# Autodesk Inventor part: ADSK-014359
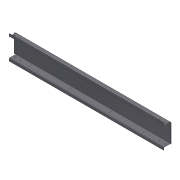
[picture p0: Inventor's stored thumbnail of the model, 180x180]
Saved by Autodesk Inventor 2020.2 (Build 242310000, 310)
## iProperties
Created: 2000-02
Part Number: ADSK-014359
Document SubType Name: Tôlerie
Designer: gpurviance
Material: 1.0312 DC05
Density: 1 g/cm^3
Sheet Metal Rule: Stahlblech 1.0312 - DC05 -   3.0 mm
Appearance: Metal-Steel(Polish)
Mass: 2976.02 g
Surface Area: 20026.5 cm^2
Volume: 2976.02 cm^3
Sheet Metal Width: 483,143 mm
Sheet Metal Length: 2072,093 mm
Sheet Metal Area: 1001118,030 mm^2
Flat Pattern Width: 48.3143 cm
Flat Pattern Length: 207.209 cm
Flat Pattern Area: 10011.2 cm^2
Control State: 0
Master: False
Checked Out: False
Shininess: 57.0
Length Units: 11269
Angle Units: 11279
Time Units: 11290
Mass Units: 11283
Length Display Precision: 3
Angle Display Precision: 2
Compacted: True
Cutlength: 500 SI (19.38 X 25.80)
Material Desc: SHEET,SS,11 GA
Material_Number: A084638
G_L: 483,1x2072,1 mm
Thickness: 3,000 mm
Dimensions: 314x92x2068,6 mm
Mass: 2,976 kg
Semi finished: Stahlblech 1.0312 - DC05 -   3.0 mm
VLT_Material: 1.0312 DC05
DocNumber: ADSK-014359
Folder: 01 - Themengebiete\Simplification\01 - Packaging machine\
Original: C:\AB_Vault\CAD\01 - Themengebiete\Simplification\01 - Packaging machine\Parts\ADSK-011414.ipt
VDS_Category: 3D Komponenten
VDS_NumSchm: Autodesk
Density: 0.0
Volumn: 0.0
Area: 0.0
PropertySet Name: Model Information
Author: gpurviance
Revision Number: -
Title: base
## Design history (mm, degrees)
node "Face1"
  sketch "Sketch1"
    geometry: L1 (-1017, -124)-(1017, -124); L2 (1017, -124)-(1017, 124); L3 (1017, 124)-(-1017, 124); L4 (-1017, 124)-(-1017, -124); 3 further points
    constraints: 8 end point, 2 midpoint, 2 parallel, 1 horizontal, 1 horizontal alignment, 1 perpendicular, 1 vertical alignment
    dimensions: "Width" = 248 distance between parallel lines of L1 L3; "Length" = 2034 distance between parallel lines of L2 L4
node "Lasche7"
node "Lasche8"
mirror "Spiegeln1"
node "Lasche11"
node "Hole1" dims "d24" = 9, "d25" = 9.525, "d26" = 6.35, "d27" = 60 deg, "d28" = 19.05, "d29" = 118 deg, "d190" = 6
  sketch "Sketch8"
    geometry: L1 (1933, 46.9)-(2009, 46.9); L2 (0, -0.1)-(2034, -0.1) reference; L3 (615.95, 79.9)-(2034, 5.9) reference
    constraints: 2 end point, 1 horizontal, 1 horizontal alignment
    dimensions: "d187" = 76 distance of L1.start L1.end; "d188" = 47 distance between parallel lines of L1 L2; "d189" = 25 distance from line of L3 L1.end
mirror "Spiegeln2"
node "Hole3" dims "d42" = 9, "d43" = 9.525, "d44" = 6.35, "d45" = 60 deg, "d46" = 19.05, "d47" = 118 deg, "d194" = 6
  sketch "Sketch10"
    geometry: L1 (632.975, -139.575)-(332.975, -139.575); L2 (332.975, -139.575)-(332.975, -431.575); L3 (332.975, -431.575)-(632.975, -431.575); L4 (632.975, -431.575)-(632.975, -139.575); L5 (307.975, -412.575)-(307.975, -442.575) reference; 6 further points
    constraints: 8 end point, 4 coincident, 2 parallel, 1 horizontal, 1 horizontal alignment, 1 midpoint, 1 perpendicular
    dimensions: "d191" = 292 distance of L1.end L2.end; "d192" = 300 distance of L1.start L1.end; "d193" = 25 distance between parallel lines of L5 L2
sketch "Skizze25"
  geometry: L1 (222, 59)-(1812, 59); L2 (1812, 59)-(1812, 27); L3 (1812, 27)-(222, 27); L4 (222, 27)-(222, 59); L5 (0, -6)-(2034, -6) reference; L6 (1.608, 86)-(2032.392, 86) reference; 7 further points
  constraints: 8 end point, 4 point on line, 3 vertical alignment, 2 midpoint, 2 parallel, 1 horizontal, 1 perpendicular
  dimensions: "d206" = 1590 distance of L2.end L3.end; "d207" = 32 distance of L1.end L2.end; "d217" = 27 distance between parallel lines of L6 L1; "d218" = 530 distance of L3.end point (752, 27) (derived); "d219" = 530 distance of L2.end point (1282, 27) (derived)
hole "Bohrung12" sketch "Skizze25" at (222, 59), (222, 27), (1812, 59), (1812, 27), (1282, 59), (1282, 27), (752, 59), (752, 27) diameter "d209" = 6.6; stored, may be unused: countersink angle "d213" = 90 deg, drill point angle "d215" = 118 deg; dims "d210" = 6, "d211" = 12.6, "d212" = 2, "d214" = 3 (derived)
sketch "Skizze24"
  geometry: L1 (1812, -59)-(222, -59); L2 (222, -59)-(222, -27); L3 (222, -27)-(1812, -27); L4 (1812, -27)-(1812, -59); L5 (0, 0)-(0, -80) reference; L6 (0, 6)-(2034, 6) reference; L7 (2032.392, -86)-(1.608, -86) reference; 9 further points
  constraints: 8 end point, 6 point on line, 4 vertical alignment, 2 midpoint, 2 parallel, 1 horizontal, 1 perpendicular
  dimensions: "d195" = 32 distance of L3.end L1.start; "d196" = 1590 distance of L1.start L1.end; "d216" = 27 distance between parallel lines of L7 L1; "d220" = 530 distance from line of L2 point (752, -59) (derived); "d221" = 530 distance from line of L4 point (1282, -59) (derived); "d236" = 80 distance from line of L4 point (1732, -27)
hole "Bohrung11" sketch "Skizze24" at (222, -59), (222, -27), (1282, -59), (1282, -27), (752, -59), (752, -27), (1732, -27), (1732, -59) diameter "d199" = 6.6; stored, may be unused: countersink angle "d203" = 90 deg, drill point angle "d205" = 118 deg; dims "d200" = 6, "d201" = 12.6, "d202" = 2, "d204" = 3 (derived)
sketch "Skizze26"
  geometry: L1 (1033, -15)-(1001, -15); L2 (0, 0)-(2034, 0) reference; L3 (1033, -299)-(1001, -299); L4 (0, -314)-(2034, -314) reference; 9 further points
  constraints: 4 end point, 4 midpoint, 3 coincident, 2 horizontal, 2 vertical alignment, 1 point on line
  dimensions: "d222" = 32 distance of L1.start L1.end; "d223" = 15 distance between parallel lines of L1 L2; "d224" = 32 distance of L3.start L3.end (derived); "d225" = 15 distance between parallel lines of L4 L3 (derived)
hole "Bohrung13" sketch "Skizze26" at (1033, -15), (1001, -15), (1032.825, -299), (1001, -299) diameter "d226" = 6.6; stored, may be unused: countersink angle "d230" = 90 deg, drill point angle "d232" = 118 deg; dims "d227" = 6, "d228" = 10.4, "d229" = 2, "d231" = 3 (derived)
pattern_linear "Rechteckige Anordnung1" dims "d235" = 480
node "Solide1"
node "Corps solides"
node "Corps surfaciques"
node "Plate1" dims "d126" = 3 (derived)
sketch "Skizze18"
  geometry: L1 through (-1017, 0) direction (1, 0); L2 through (0, 46) direction (0, 1); L3 (0, 92)-(-2034, 92); L4 (-2034, 92)-(-2034, 0)
  constraints: 6 end point, 1 horizontal, 1 perpendicular, 1 vertical
feature "Grobblech8" dims "d126" = 3 (derived), "d127" = 3 (derived), "d128" = 1.5 (derived), "d129" = 6 (derived), "d130" = 3 (derived), "d131" = 92, "d132" = 90 deg, "d133" = 3 (derived), "d134" = 12 (derived), "d135" = 3 (derived), "d136" = 3 (derived), "SeamGap" = 0.00508
feature "Biegung7" dims "d126" = 3 (derived), "d127" = 3 (derived), "d128" = 1.5 (derived), "d129" = 6 (derived), "d130" = 3 (derived), "d131" = 92, "d132" = 90 deg, "d133" = 3 (derived), "SeamGap" = 0.00508
feature "Ecke1" dims "d131" = 92, "d132" = 90 deg, "d134" = 12 (derived), "d135" = 3 (derived), "d136" = 3 (derived)
sketch "Skizze19"
  geometry: L1 through (-1017, 0) direction (1, -1.92e-34); L2 through (0, 18) direction (2.07e-34, 1); L3 (0, 36)-(-2034, 36); L4 (-2034, 36)-(-2034, 0)
  constraints: 6 end point, 1 horizontal, 1 perpendicular, 1 vertical
feature "Grobblech9" dims "d126" = 3 (derived), "d137" = 3 (derived), "d138" = 1.5 (derived), "d139" = 6 (derived), "d140" = 3 (derived), "d141" = 36, "d142" = 90 deg, "d143" = 3 (derived), "d144" = 12 (derived), "d145" = 3 (derived), "d146" = 3 (derived), "SeamGap" = 0.00508
feature "Biegung8" dims "d126" = 3 (derived), "d137" = 3 (derived), "d138" = 1.5 (derived), "d139" = 6 (derived), "d140" = 3 (derived), "d141" = 36, "d142" = 90 deg, "d143" = 3 (derived), "SeamGap" = 0.00508
feature "Ecke2" dims "d141" = 36, "d142" = 90 deg, "d144" = 12 (derived), "d145" = 3 (derived), "d146" = 3 (derived)
sketch "Skizze22"
  geometry: L1 through (-118, 0) direction (1, 0); L2 through (0, 10) direction (0, 1); L3 (0, 20)-(-236, 20); L4 (-236, 20)-(-236, 0)
  constraints: 6 end point, 1 horizontal, 1 perpendicular, 1 vertical
feature "Grobblech12" dims "d126" = 3 (derived), "d167" = 3 (derived), "d168" = 1.5 (derived), "d169" = 6 (derived), "d170" = 3 (derived), "d171" = 20, "d172" = 30 deg, "d173" = 3 (derived), "d174" = 12 (derived), "d175" = 3 (derived), "d176" = 3 (derived), "SeamGap" = 0.00508
feature "Biegung11" dims "d126" = 3 (derived), "d167" = 3 (derived), "d168" = 1.5 (derived), "d169" = 6 (derived), "d170" = 3 (derived), "d171" = 20, "d172" = 30 deg, "d173" = 3 (derived), "SeamGap" = 0.00508
feature "Ecke5" dims "d171" = 20, "d172" = 30 deg, "d174" = 12 (derived), "d175" = 3 (derived), "d176" = 3 (derived)
feature "Definition1"
other parameters: "Thickness" = 3 (derived), "BendRadius" = 3 (derived), "BendReliefWidth" = 3 (derived), "BendReliefDepth" = 1.5 (derived), "CornerReliefSize" = 12 (derived), "MinimumRemnant" = 6 (derived), "d2" = 3 (= BendRadius), "d3" = 85.725, "d4" = 90 deg, "d5" = 3 (= BendRadius), "d9" = 85.725, "d10" = 90 deg, "d11" = 3 (= BendRadius), "d15" = 19.05, "d16" = 30 deg, "d17" = 3 (= BendRadius), "d18" = 19.05, "d19" = 30 deg, "d20" = 3 (= BendRadius), "TransitionRadius" = 3 (derived), "TailleRayonJacobi" = 3 (derived), "TailleJeu" = 3 (derived), "BendRadius" = 3, "BendReliefDepth" = 1.5, "BendReliefWidth" = 3, "CornerReliefSize" = 12, "Length" = 2034, "MinimumRemnant" = 6, "TailleJeu" = 3, "TailleRayonJacobi" = 3, "Thickness" = 3, "TransitionRadius" = 3, "Width" = 248
